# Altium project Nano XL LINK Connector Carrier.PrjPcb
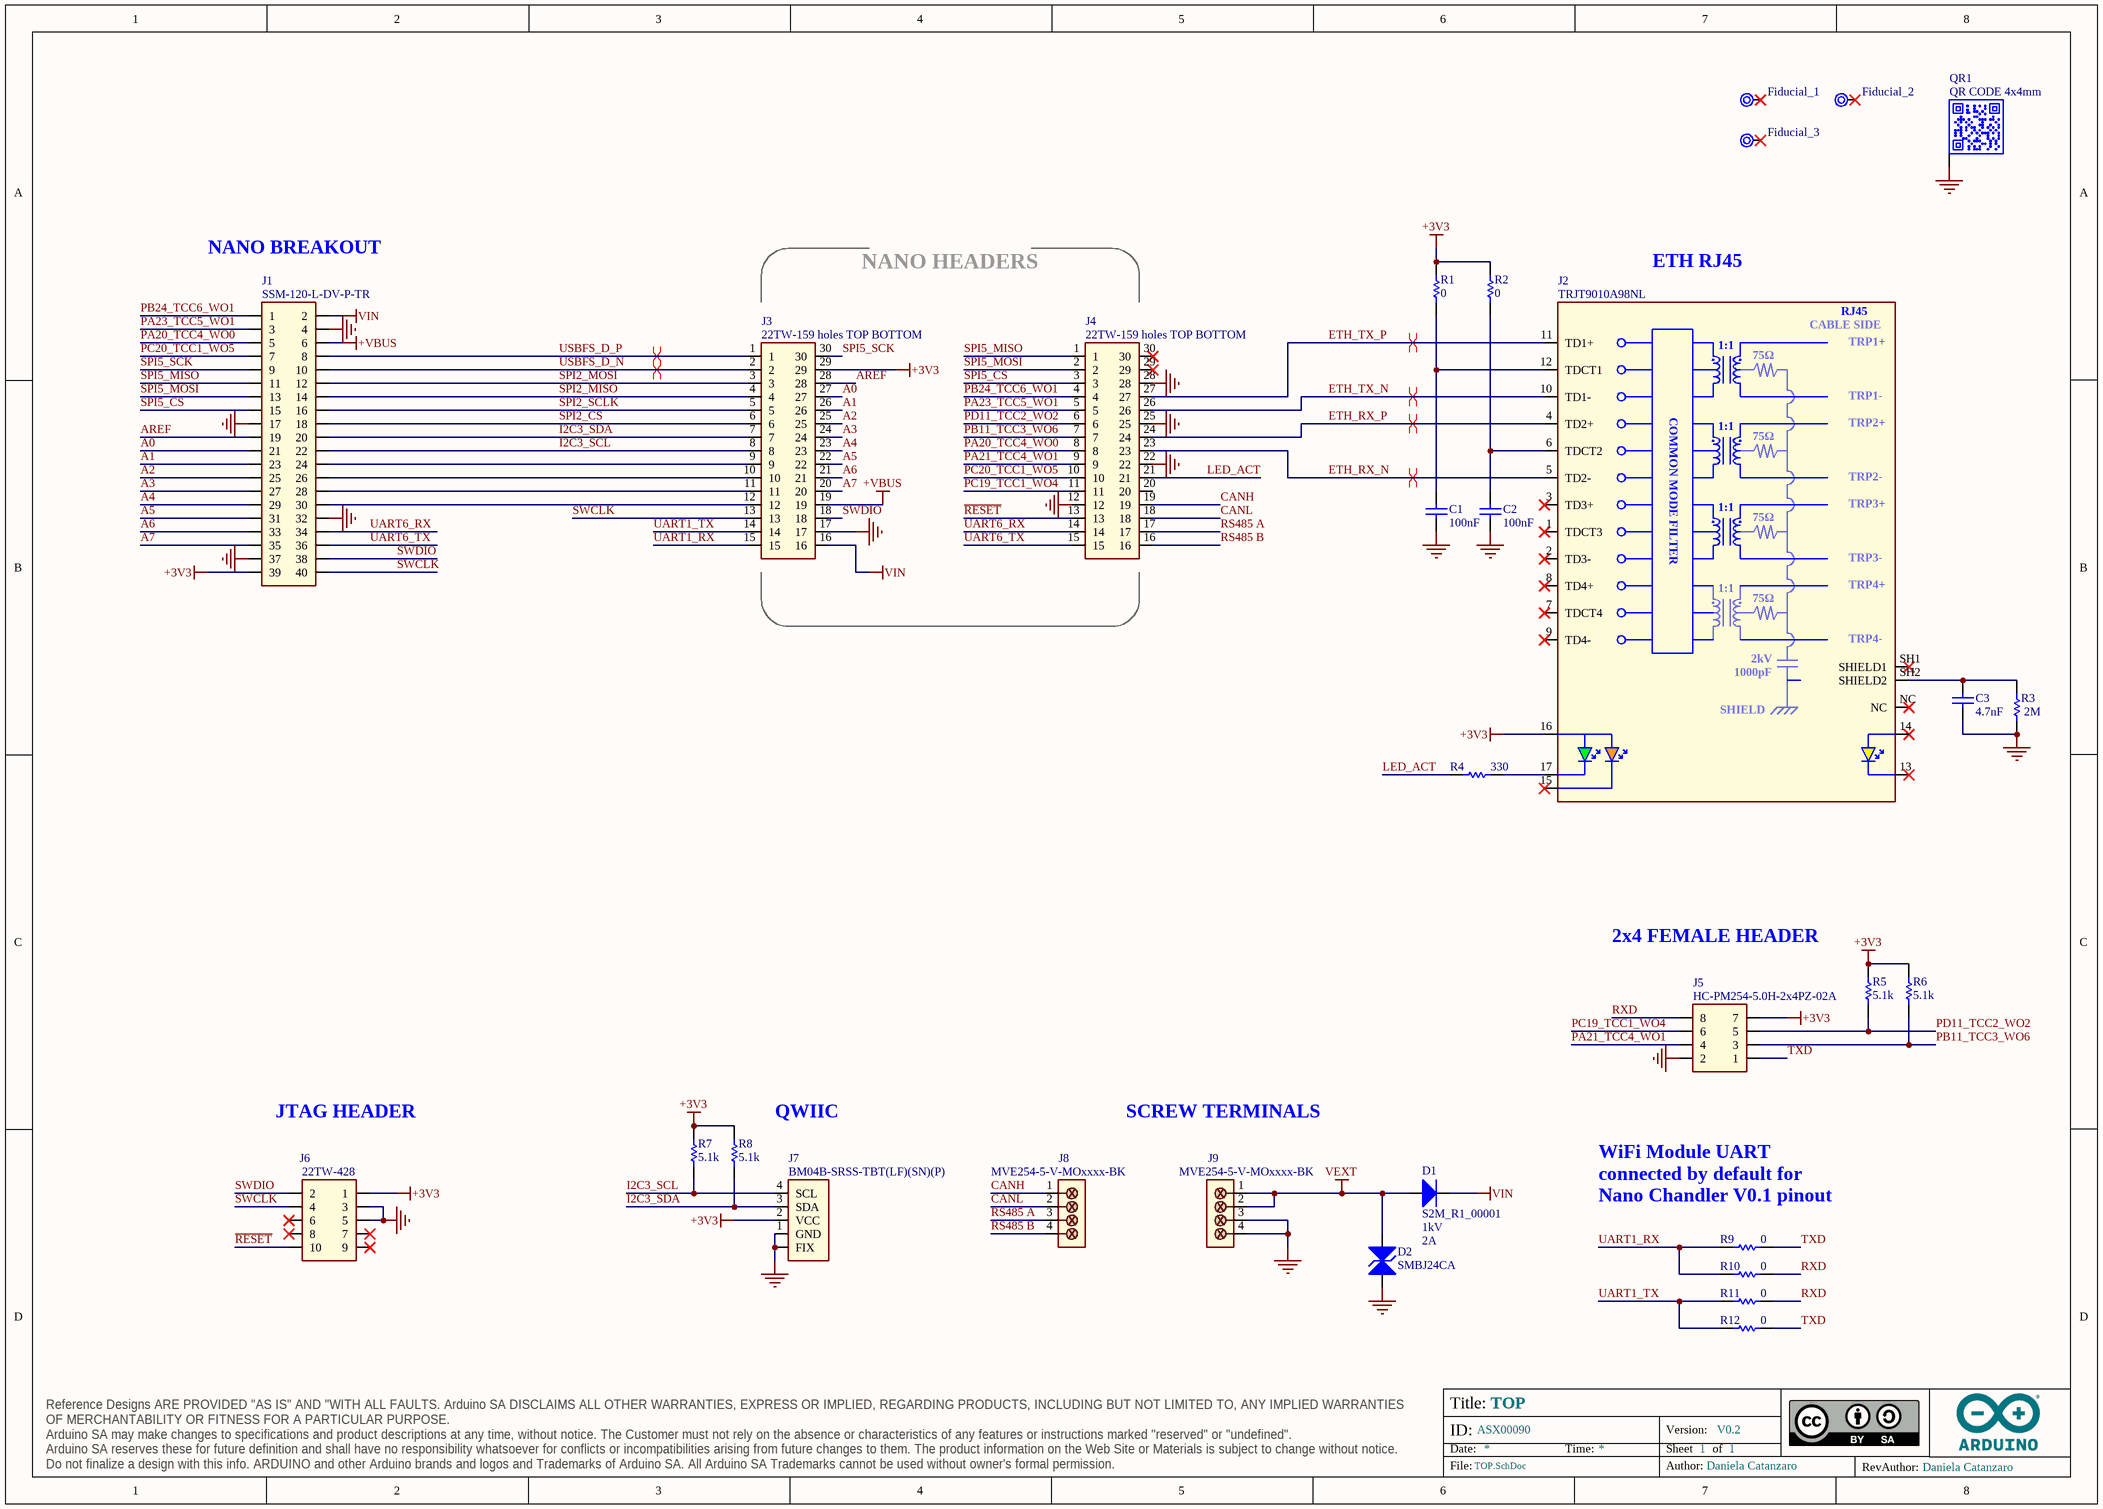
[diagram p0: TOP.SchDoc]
ASSEMBLY_BGA: _; ASSEMBLY_PRESSFIT: _; ASSEMBLY_SMD: X; ASSEMBLY_THT: X; BOARD_CODENAME: MONICA; BOARD_INFO_AUTHOR: Daniela Catanzaro; BOARD_INFO_AUTHOR_REV: Daniela Catanzaro; BOARD_INFO_Er: _; BOARD_INFO_FLEX: _; BOARD_INFO_FR4: X; BOARD_INFO_FR4_HTG: _; BOARD_INFO_IPC1: _; BOARD_INFO_IPC2: X; BOARD_INFO_IPC3: _; BOARD_INFO_IPC_NA: _; BOARD_INFO_NUMBER_OF_LAYERS: 4; BOARD_INFO_PCB_SIZE: 88.7x71.8mm; BOARD_INFO_POLYMIDE: _; BOARD_INFO_RIGID: X; BOARD_INFO_RIGID/FLEX: _; BOARD_INFO_TBD: _; BOARD_INFO_THICKNESS: 1.6mm; DRILLS_BLIND: _; DRILLS_BURIED: _; DRILLS_COPPER_FILLING: _; DRILLS_FULL: X; DRILLS_LASER: _; DRILLS_PRESSFIT: _; DRILLS_RESIN_FILLING: _; DRILLS_SLOT: _; DRILLS_SOLDER_FILLING: X; FINISH_ADJUSTMENTS: _; FINISH_EDGE_PLATING: _; FINISH_ENIG: _; FINISH_HAL: _; FINISH_HAL_LF: X; FINISH_NI/AU: _; FINISH_SILK_BOTTOM: X; FINISH_SILK_COLOR: WHITE; FINISH_SILK_TOP: X; FINISH_SN/PB: _; FINISH_SOLDERMASK_BOTTOM: X; FINISH_SOLDERMASK_COLOR: BLUE; FINISH_SOLDERMASK_PEELABLE_BOTTOM: _; FINISH_SOLDERMASK_PEELABLE_COLOR: _; FINISH_SOLDERMASK_PEELABLE_TOP: _; FINISH_SOLDERMASK_TOP: X; FINISH_TABS: _; FINISH_TBD: _; INSULATION_MIN_INNER: 0.127mm; INSULATION_MIN_OUTER: 0.127mm; PANEL_MILLING: X; PANEL_NOT_REQUESTED: _; PANEL_NUMBER_OF_FIGURES: 10; PANEL_PROVIDED: X; PANEL_REQUESTED: _; PANEL_SCORING: X; PANEL_SIZE: 284.7x157.16mm; PANEL_TABS: _; SKU: ASX00090; TRACK_MIN_WIDTH_INNER: 0.127mm; TRACK_MIN_WIDTH_OUTER: 0.127mm; Version: V0.2; VIA_1: _; VIA_1_HOLE_MM: _; VIA_1_PAD_MM: _; VIA_2: _; VIA_2_HOLE_MM: _; VIA_2_PAD_MM: _; VIA_3: _; VIA_3_HOLE_MM: _; VIA_3_PAD_MM: _; VIA_4: _; VIA_4_HOLE_MM: _; VIA_4_PAD_MM: _; VIA_5: _; VIA_5_HOLE_MM: _; VIA_5_PAD_MM: _; VIA_THROUGH: X; VIA_THROUGH_HOLE_MM: 0.3; VIA_THROUGH_PAD_MM: 0.6
1 sheet, 30 parts. Net scope: hierarchical (ports join the sheet entries above them; power ports are global).
Board files: PCB.PcbDoc, PANEL.PcbDoc

## Sheet TOP.SchDoc: TOP
size A3; Revision: V0.2; SheetNumber: 1; SheetTotal: 1

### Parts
C1  value 100nF  [CAP-0603]  (hidden comment: 0603B104K500CT)
C2  value 100nF  [CAP-0603]  (hidden comment: 0603B104K500CT)
C3  value 4.7nF  [CAP-0805]  (hidden comment: FV21X472K102ECG)
D1  S2M_R1_00001  Max Reverse Voltage (DC): 1kV  Forward Current: 2A  [SMB]
D2  SMBJ24CA  [SMB_NOPOLARITY]
Fiducial_1  Fiducial mark 1mm with 2mm solder  [Fiducial mark 1mm with circle-Footprint-1]  (value not drawn)  (no BOM)
Fiducial_2  Fiducial mark 1mm with 2mm solder  [Fiducial mark 1mm with circle-Footprint-1]  (value not drawn)  (no BOM)
Fiducial_3  Fiducial mark 1mm with 2mm solder  [Fiducial mark 1mm with circle-Footprint-1]  (value not drawn)  (no BOM)
J1  SSM-120-L-DV-P-TR  [SSM-120-L-DV-P-TR]
J2  TRJT9010A98NL  [TRJT9010A98NL]
J3  22TW-159 holes TOP BOTTOM  [HLE-115-02-F-DV holes TOP BOTTOM]
J4  22TW-159 holes TOP BOTTOM  [HLE-115-02-F-DV holes TOP BOTTOM]
J5  HC-PM254-5.0H-2x4PZ-02A  [HEADER FEMALE 2.54mm TH 2x4 5mm height]
J6  22TW-428  [FTSH-105-01-F-DV-Footprint-1]
J7  BM04B-SRSS-TBT(LF)(SN)(P)  [BM04B-SRSS-TB]
J8  MVE254-5-V-MOxxxx-BK  [MVE254-5-V-MOxxxx-BK]
J9  MVE254-5-V-MOxxxx-BK  [MVE254-5-V-MOxxxx-BK]
QR1  QR CODE 4x4mm  [QR CODE 4x4mm]  (no BOM)
R1  value 0  [RES-0603]  (hidden comment: CRCW06030000Z0EAC)
R2  value 0  [RES-0603]  (hidden comment: CRCW06030000Z0EAC)
R3  value 2M  [RES-0603]  (hidden comment: RC0603FR-072ML)
R4  value 330  [RES-0603]  (hidden comment: CRCW0603330RFKEAC)
R5  value 5.1k  [RES-0603]  (hidden comment: CR0603AFX-5101EAS)
R6  value 5.1k  [RES-0603]  (hidden comment: CR0603AFX-5101EAS)
R7  value 5.1k  [RES-0603]  (hidden comment: CR0603AFX-5101EAS)
R8  value 5.1k  [RES-0603]  (hidden comment: CR0603AFX-5101EAS)
R9  value 0  [RES-0603]  (hidden comment: CRCW06030000Z0EAC)
R10  value 0  [RES-0603]  (hidden comment: CRCW06030000Z0EAC)
R11  value 0  [RES-0603]  (hidden comment: CRCW06030000Z0EAC)
R12  value 0  [RES-0603]  (hidden comment: CRCW06030000Z0EAC)

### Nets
+3V3: J1.39 J2.16(COMMON_ANODE) J3.29 J5.7 J6.1 J7.2(VCC) R1.2 R2.2 R5.2 R6.2 R7.2 R8.2
+VBUS: J1.6 J3.19
GND: C1.1 C2.1 C3.1 D2.1(A1) J1.4 J1.17 J1.32 J1.37 J3.17 J4.12 J4.22 J4.25 J4.28 J5.2 J6.3 J6.5 J7.1(GND) J7.FIX J9.3 J9.4 QR1.PAD R3.1
VEXT: D1.A D2.2(A2) J9.1 J9.2
VIN: D1.C J1.2 J3.16
A0: J1.21 J3.27  [project net A0_1]
A1: J1.23 J3.26  [project net A1_1]
A2: J1.25 J3.25  [project net A2_1]
A3: J1.27 J3.24  [project net A3_1]
A4: J1.29 J3.23  [project net A4_1]
A5: J1.31 J3.22  [project net A5_1]
A6: J1.33 J3.21  [project net A6_1]
A7: J1.35 J3.20  [project net A7_1]
AREF: J1.19 J3.28  [project net AREF_1]
CANH: J4.19 J8.1  [project net CANH_1]
CANL: J4.18 J8.2  [project net CANL_1]
ETH_RX_N: J2.5(TD2-) J4.23  [project net ETH_RX_N_1]
ETH_RX_P: J2.4(TD2+) J4.24  [project net ETH_RX_P_1]
ETH_TX_N: J2.10(TD1-) J4.26  [project net ETH_TX_N_1]
ETH_TX_P: J2.11(TD1+) J4.27  [project net ETH_TX_P_1]
I2C3_SCL: J1.22 J3.8 J7.4(SCL) R7.1  [project net I2C3_SCL_1]
I2C3_SDA: J1.20 J3.7 J7.3(SDA) R8.1  [project net I2C3_SDA_1]
LED_ACT: J4.21 R4.1  [project net LED_ACT_1]
PA20_TCC4_WO0: J1.5 J4.8  [project net PA20_TCC4_WO0_1]
PA21_TCC4_WO1: J4.9 J5.4  [project net PA21_TCC4_WO1_1]
PA23_TCC5_WO1: J1.3 J4.5  [project net PA23_TCC5_WO1_1]
PB11_TCC3_WO6: J4.7 J5.3 R6.1  [project net PB11_TCC3_WO6_1]
PB24_TCC6_WO1: J1.1 J4.4  [project net PB24_TCC6_WO1_1]
PC19_TCC1_WO4: J4.11 J5.6  [project net PC19_TCC1_WO4_1]
PC20_TCC1_WO5: J1.7 J4.10  [project net PC20_TCC1_WO5_1]
PD11_TCC2_WO2: J4.6 J5.5 R5.1  [project net PD11_TCC2_WO2_1]
~{RESET}: J4.13 J6.10  [project net ~{RESET}_1]
RS485 A: J4.17 J8.3  [project net RS485 A_1]
RS485 B: J4.16 J8.4  [project net RS485 B_1]
RXD: J5.8 R10.2 R11.2  [project net RXD_1]
SPI2_CS: J1.18 J3.6  [project net SPI2_CS_1]
SPI2_MISO: J1.14 J3.4  [project net SPI2_MISO_1]
SPI2_MOSI: J1.12 J3.3  [project net SPI2_MOSI_1]
SPI2_SCLK: J1.16 J3.5  [project net SPI2_SCLK_1]
SPI5_CS: J1.15 J4.3  [project net SPI5_CS_1]
SPI5_MISO: J1.11 J4.1  [project net SPI5_MISO_1]
SPI5_MOSI: J1.13 J4.2  [project net SPI5_MOSI_1]
SPI5_SCK: J1.9 J3.30  [project net SPI5_SCK_1]
SWCLK: J1.40 J3.13 J6.4  [project net SWCLK_1]
SWDIO: J1.38 J3.18 J6.2  [project net SWDIO_1]
TXD: J5.1 R9.2 R12.2  [project net TXD_1]
UART1_RX: J3.15 R9.1 R10.1  [project net UART1_RX_1]
UART1_TX: J3.14 R11.1 R12.1  [project net UART1_TX_1]
UART6_RX: J1.34 J4.14  [project net UART6_RX_1]
UART6_TX: J1.36 J4.15  [project net UART6_TX_1]
USBFS_D_N: J1.10 J3.2  [project net USBFS_D_N_1]
USBFS_D_P: J1.8 J3.1  [project net USBFS_D_P_1]
NetC1_2: C1.2 J2.12(TDCT1) R1.1
NetC2_2: C2.2 J2.6(TDCT2) R2.1
NetC3_2: C3.2 J2.SH2(SHIELD2) R3.2
NetJ1_24: J1.24 J3.9
NetJ1_26: J1.26 J3.10
NetJ1_28: J1.28 J3.11
NetJ1_30: J1.30 J3.12
NetJ2_17: J2.17(GREEN_CATHODE) R4.2

Not connected (* = marked no-connect by the designer): Fiducial_1 1*; Fiducial_2 1*; Fiducial_3 1*; J2 1(TDCT3)* 2(TD3-)* 3(TD3+)* 7(TDCT4)* 8(TD4+)* 9(TD4-)* 13(YELLOW_CATHODE)* 14(YELLOW_ANODE)* 15(ORANGE_CATHODE)* NC* SH1(SHIELD1)*; J4 20 29* 30*; J6 6* 7* 8* 9*

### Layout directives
differential pair; differential pair class USBC_FS: USBFS_D_N_1, USBFS_D_P_1
differential pair; differential pair class ETH: ETH_RX_N_1, ETH_RX_P_1, ETH_TX_N_1, ETH_TX_P_1

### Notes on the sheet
- NANO BREAKOUT
- NANO HEADERS
- ETH RJ45
- (near R5) 2x4 FEMALE HEADER
- JTAG HEADER
- QWIIC
- SCREW TERMINALS
- (near R9) WiFi Module UART connected by default for Nano Chandler V0.1 pinout

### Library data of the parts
C1 C2 = C0043-A.16: CAP CHIP 0603 100nF 10% 50V X7R; Manufacturer: Walsin; Code Arduino: 0015
C3 = C0059-A.16: CAP CHIP 0805 4.7nF 10% 1000V X7R; Manufacturer: PSA Shenzen; Voltage: 1kV; Code Arduino: 0689
D1 = D0003-A.4: DIODE SMD 1000V 2A SMB; Manufacturer: Panjit; Forward Voltage: 1.1V; Code Arduino: D0003
D2 = D0070-A.3: TVS BIDIRECTIONAL SMD, Reverse standoff 24V, Breakdown min 26.7V, Clamping max 39.8V, 600W, SMB; Manufacturer: Littlefuse; V(BR) Typ (V): 26.7; Code Arduino: D0070
Fiducial_1-Fiducial_3 = UT0024-A.6
J1 = J0475-A.2: PIN HEADER FEMALE SMD 2.54mm VERT. 2x20POS height 7.5mm; Manufacturer: Samtech; Code Arduino: J0475
J2 = J0561-A.4: CONN ETH 1x1 RJ45 TH 10/100/1000/2500 integrated magnetics, LED GREEN/YELLOW/ORANGE, micro profile 17.8x24.2x11.55mm; Manufacturer: TRXCOM; Code Arduino: J0561
J3 J4 = J0233-A.21: CONN SMD 2.54mm BOARD FEMALE 30 POS 15X2 holes TOP BOTTOM; Manufacturer: 4UCONN; Code Arduino: J0233
J5 = J0596-A.1: HEADER 2.54mm TH 2x4POS FEMALE VERTICAL heigth 5mm; Manufacturer: Hong Cheng; Code Arduino: J0596
J6 = J0089-A.11: CONN HEADER SMD 10POS 2x5 1.27MM JTAG reel, capsfor pick and place; Manufacturer: 4UCON; Current Rating: 1.75A; Connector Type: Male Pin; Code Arduino: J0089; Gender: Male
J7 = J0478-A.4: CONN JST 4POS VERTICAL 1mm pitch, color neutral, suction tape, tin, QWIIC; Code Arduino: J0478
J8 J9 = J0482-A.1: CONN SCREW TERMINAL, pitch 5mm, 4POS, 16A, 450V, 2.5mm^2 14AWG, dovetail, BLACK, screw Phillips, housing 20x16.8x8.9mm; Manufacturer: Euroclamp; Code Arduino: J0482
QR1 = QR-0001-A.5: QR CODE 4x4mm on layer 34 (This is not a component); Code Arduino: QRCODE_4x4mm
R1 R2 R9-R12 = R0096-A.23: RES CHIP 0603 0R 1/10W; Manufacturer: Vishay; Power: 100mW; Code Arduino: 0233; Tolerance: 0%; Temperature coefficient: 0ppm
R3 = R0428-A.2: RES CHIP 0603 2M 1% 1/10W; Manufacturer: YAGEO; Power: 100mW; Temperature coefficient: 100ppm; Code Arduino: R0428
R4 = R0123-A.23: RES CHIP 0603 330R 1% 1/10W; Manufacturer: Vishay; Power: 100mW; Temperature coefficient: 100ppm; Code Arduino: 0049
R5-R8 = R0239-A.12: RES CHIP 0603 5k1 1% 1/10W; Manufacturer: Bourns; Code Arduino: R0239; Power: 100mW; Temperature coefficient: 100ppm

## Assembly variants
ASX00090: not fitted R1 R2 R10 R12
